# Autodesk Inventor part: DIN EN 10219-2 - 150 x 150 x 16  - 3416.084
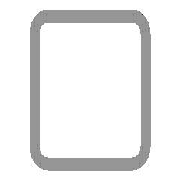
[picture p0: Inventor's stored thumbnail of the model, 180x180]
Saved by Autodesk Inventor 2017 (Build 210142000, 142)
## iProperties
IsCustomPart: 1
Created: 2016-02
Part Number: DIN EN 10219-2 - 150 x 150 x 16  - 3416.084
Material: Steel, Mild
Description: Cold formed welded structural hollow sections of non-alloy and fine grain structural steel
Document SubType Name: Modeling
Standard: DIN
Designer: iusti
Standard Revision: 2006-07
Standards Organization: DIN
Language: en-US
Size Designation: 150 x 150 x 16
Categories: <MemberInstance><Categories><Category DisplayName="Structural Shapes" InternalName="089c4875-fa83-4c05-b084-43b9cc11f5ed" Mnemonic="GRDR"><CategoryParameter Dis
Stock Number: 150 x 150 x 16
Density: 7.85 g/cm^3
Appearance: Semi-Polished
Mass: 187360 g
Surface Area: 30123 cm^2
Volume: 23867.5 cm^3
_CCFamilyMember: 76
_CCFamilyDisplayName: DIN EN 10219-2 (Square Hollow Section - Cold Formed) - Cold formed welded structural hollow sections of non-alloy and fine grain structural steel
_FrameMemberDoc: Frame Member File
_Version: 15.0.0
_GetPNFromCC: 1
G_L: 3416.084 mm
G_W: 150.000 mm
G_H: 150.000 mm
+04F2D6EA-35C4-4CFB-B988-CDC8EB8D103C+CUTDETAIL1: Cut
+DAF749EB-893C-4754-AD4A-1A621FA4CB9E+CUTDETAIL2: Cut
Author: iusti
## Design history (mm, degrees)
node "Start plane"
node "End plane"
sketch "Sketch"
  geometry: L1 (-75, -27)-(-75, 27); L2 (-27, 75)-(27, 75); L3 (75, 27)-(75, -27); L4 (27, -75)-(-27, -75); L5 (-27, 59)-(27, 59); L6 (59, 27)-(59, -27); L7 (27, -59)-(-27, -59); L8 (-59, -27)-(-59, 27); L9 (0, 118.918)-(0, -118.918) reference; L10 (-118.918, 0)-(118.918, 0) reference; A1 r 48 centre (-27, -27) between (-75, -27) and (-27, -75); A2 r 48 centre (-27, 27) between (-27, 75) and (-75, 27); A3 r 48 centre (27, 27) between (75, 27) and (27, 75); A4 r 48 centre (27, -27) between (27, -75) and (75, -27); A5 r 32 centre (-27, 27) between (-27, 59) and (-59, 27); A6 r 32 centre (27, 27) between (59, 27) and (27, 59); A7 r 32 centre (27, -27) between (27, -59) and (59, -27); A8 r 32 centre (-27, -27) between (-59, -27) and (-27, -59)
  constraints: 16 end point, 16 point on circle, 8 centre point, 8 tangent, 4 parallel, 3 equal radius, 2 perpendicular, 7 other
  dimensions: "d7" = 48 radius of A1 (= G_IR); "d10" = 150 distance between parallel lines of L2 L4 (= G_H); "d11" = 150 distance between parallel lines of L1 L3 (= G_W); "d12" = 16 distance between parallel lines of L3 L6 (= G_T); "d15" = 75 distance between parallel lines of L2 L10 (= 0.5 x d10); "d16" = 75 distance between parallel lines of L9 L3 (= 0.5 x d11)
extrude "Body" new body sketch "Sketch" stored distance "d3" = 3416.08372 (= G_L); taper "d4" = 0 deg
node "Driven Length"
  sketch "Sketch3"
    geometry: L1 (0, 0)-(10, 0) reference
    constraints: 2 end point, 1 horizontal
  workplane "Work Plane3"
  sketch "Sketch4"
    geometry: L1 (-2, 55.969)-(12, 55.969) reference; L2 (-2, 3472.052)-(12, 3472.052) reference
    dimensions: "d18" = 3416.08372 distance between parallel lines of L1 L2 (derived)
workplane "Work Plane4"
split "Split1"
workplane "Work Plane5"
split "Split2"
body "Solid1"
other parameters: "G_W" = 150 [user parameter; used in 1 equation term], "G_H" = 150 [user parameter; used in 1 equation term], "G_T" = 16 [user parameter; used in 1 equation term], "G_IR" = 48 [user parameter; used in 1 equation term], "G_L" = 3416.08372 (= d18) [user parameter; used in 1 equation term], "G_OFFSET_START" = -55.96865 [user parameter; used in 1 equation term], "G_OFFSET_END" = -13.90929 [user parameter; used in 1 equation term], "d13" = 55.96865 (= -G_OFFSET_START), "d14" = 3472.05237 (= G_OFFSET_END + B_L), "B_L" = 3485.96166 [user parameter; used in 1 equation term], "d17" = 90 deg
